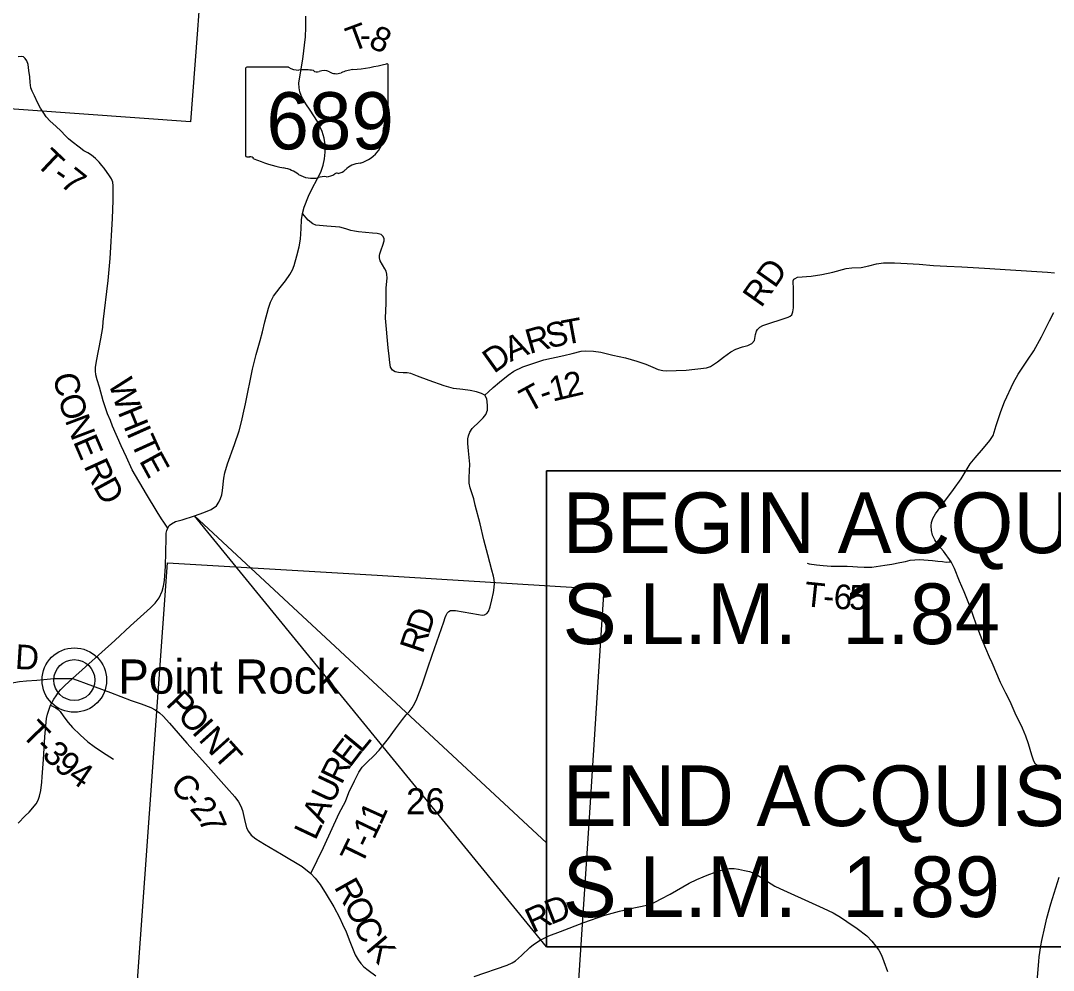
# Model space of a CAD drawing. Extents: x 0 to 34, y 0 to 22.
# Drawn here: x 4.807 to 7.19, y 15.87 to 18.062 of the extents above; entities that cross this region are included whole.
import ezdxf

# ---------------------------------------------------------------- set-up
doc = ezdxf.new("R2010")
doc.units = 0
for name, color, linetype in [('GM_X_Corporation', 7, 'Continuous'), ('GM_X_County_Road', 7, 'Continuous'), ('GM_X_County_Road_Text', 7, 'Continuous'), ('GM_X_Section_Text', 7, 'Continuous'), ('GM_X_State_Location', 7, 'Continuous'), ('GM_X_State_Route', 7, 'Continuous'), ('GM_X_State_Shield', 7, 'Continuous'), ('GM_X_Township_Road', 7, 'Continuous'), ('GM_X_Township_Road_Text', 7, 'Continuous'), ('GM_X_Unincorporated', 7, 'Continuous'), ('GM_X_Unincorporated_Location', 7, 'Continuous'), ('GM_X_Unincorporated_Text', 7, 'Continuous'), ('SH_Text', 7, 'Continuous')]:
    doc.layers.add(name, color=color, linetype=linetype)

msp = doc.modelspace()

# ---------------------------------------------------------------- linework, layer by layer
at = {"layer": 'GM_X_Corporation'}
for points in [[(4.2512, 18.9319), (5.2756, 18.8667), (5.2491, 18.5021), (5.2146, 18.0305), (5.1989, 17.8285), (4.1811, 17.9012)], [(5.6294, 16.7819), (6.1525, 16.7497), (6.1454, 16.6317), (6.1179, 16.2098), (6.0868, 15.7303), (5.0732, 15.7926), (5.1457, 16.8107)]]:
    msp.add_lwpolyline(points, close=True, dxfattribs=at)
at = {"layer": 'GM_X_County_Road'}
for points in [[(7.1909, 16.327), (7.1802, 16.3307), (7.1695, 16.334), (7.1616, 16.3368), (7.1555, 16.3402), (7.1492, 16.3456), (7.1452, 16.3526), (7.1401, 16.3664), (7.1328, 16.3928), (7.1263, 16.4101), (7.1191, 16.4285), (7.1023, 16.4635), (7.0901, 16.4901), (7.0803, 16.5099), (7.0679, 16.534), (7.0486, 16.5795), (7.043, 16.593), (7.0261, 16.633), (7.0121, 16.6691), (6.9977, 16.7091), (6.9839, 16.7432), (6.9738, 16.7684), (6.9622, 16.7971), (6.9542, 16.8131), (6.9365, 16.8372), (6.9237, 16.8522), (6.9165, 16.8634), (6.9113, 16.8741), (6.9085, 16.885), (6.908, 16.8956), (6.9092, 16.9033), (6.9123, 16.9129), (6.9181, 16.9236), (6.9304, 16.9402), (6.9594, 16.9794), (6.9773, 17.0044), (6.9984, 17.0387), (7.0093, 17.0527), (7.0289, 17.0751), (7.0432, 17.093), (7.0509, 17.1047), (7.0584, 17.1273), (7.0686, 17.1598), (7.0772, 17.1817), (7.098, 17.227), (7.1088, 17.2457), (7.1302, 17.2782), (7.1447, 17.2997), (7.1625, 17.332), (7.1811, 17.3688), (7.1912, 17.3879)], [(4.9265, 16.5431), (4.9376, 16.5393), (4.9583, 16.5323), (5.0141, 16.5112), (5.0619, 16.493), (5.0852, 16.4849), (5.1073, 16.4762), (5.1176, 16.4708), (5.1272, 16.4645), (5.1361, 16.4563), (5.1506, 16.4406), (5.1905, 16.3943), (5.2337, 16.3465), (5.2817, 16.292), (5.3015, 16.2702), (5.3096, 16.2587), (5.3148, 16.2491), (5.3188, 16.2385), (5.3235, 16.2178), (5.3282, 16.199), (5.3329, 16.1905), (5.3393, 16.1822), (5.3499, 16.1734), (5.3696, 16.1611), (5.4086, 16.1383), (5.4563, 16.1093), (5.4768, 16.0933), (5.487, 16.0828), (5.4981, 16.0676), (5.5121, 16.0457), (5.5294, 16.0163), (5.543, 15.9915), (5.55, 15.9764), (5.5579, 15.9586), (5.5663, 15.9366), (5.5789, 15.9056), (5.5861, 15.894), (5.5924, 15.8853), (5.5992, 15.8783), (5.6088, 15.8699), (5.6263, 15.8573)], [(5.8536, 15.8557), (5.9295, 15.8818), (5.9414, 15.8871), (5.9486, 15.8921), (5.9624, 15.9044), (5.982, 15.9222), (5.9905, 15.9296), (6.0056, 15.9392), (6.0262, 15.9497), (6.0525, 15.9595), (6.1064, 15.9803), (6.1553, 15.9974), (6.1891, 16.0065), (6.2222, 16.0142), (6.2412, 16.0177), (6.261, 16.0226), (6.272, 16.0277), (6.2853, 16.0349), (6.3058, 16.0459), (6.3499, 16.0707), (6.3676, 16.0795), (6.3821, 16.086), (6.3954, 16.0909), (6.4209, 16.1), (6.4337, 16.1031), (6.4423, 16.105), (6.4535, 16.1052), (6.4638, 16.1033), (6.4772, 16.1003), (6.4888, 16.0977), (6.5009, 16.093), (6.5147, 16.0849), (6.5304, 16.0746), (6.5471, 16.0643), (6.5591, 16.0587), (6.5845, 16.0471), (6.6162, 16.0326), (6.659, 16.0137), (6.6816, 16.0029), (6.6986, 15.9927), (6.7134, 15.9829), (6.737, 15.9665), (6.7596, 15.9493), (6.7708, 15.9371), (6.7797, 15.9266), (6.7871, 15.9164), (6.7936, 15.9051), (6.7988, 15.8902), (6.8072, 15.8669)], [(7.1436, 15.7943), (7.1457, 15.802), (7.1491, 15.8155), (7.1519, 15.8304), (7.1527, 15.843), (7.1545, 15.8633), (7.1562, 15.8902), (7.1573, 15.901), (7.1608, 15.9262), (7.1632, 15.9388), (7.1702, 15.9695), (7.1749, 15.9905), (7.1844, 16.0237), (7.2038, 16.0846)]]:
    msp.add_lwpolyline(points, dxfattribs=at)
at = {"layer": 'GM_X_State_Route'}
msp.add_lwpolyline([(4.801, 16.2093), (4.8174, 16.2261), (4.8265, 16.2347), (4.8426, 16.2541), (4.8472, 16.2625), (4.8503, 16.2718), (4.8535, 16.285), (4.856, 16.3039), (4.857, 16.3162), (4.8586, 16.3365), (4.8596, 16.3568), (4.8631, 16.4088), (4.8669, 16.4512), (4.8688, 16.4615), (4.872, 16.4705), (4.8757, 16.4816), (4.8836, 16.4958), (4.8888, 16.5037), (4.8945, 16.5116), (4.9, 16.5183), (4.9093, 16.5275), (4.9265, 16.5431), (5.0242, 16.6312), (5.0608, 16.6651), (5.1065, 16.7067), (5.1175, 16.7177), (5.1265, 16.7299), (5.1336, 16.745), (5.1367, 16.7568), (5.1391, 16.7698), (5.1411, 16.8028), (5.1425, 16.867), (5.1427, 16.8789), (5.1444, 16.8853), (5.1465, 16.8908), (5.1498, 16.8964), (5.1554, 16.9008), (5.1642, 16.9058), (5.1796, 16.9098), (5.2085, 16.9189), (5.2301, 16.9263), (5.2467, 16.9335), (5.2586, 16.9421), (5.2644, 16.9502), (5.268, 16.9587), (5.2709, 16.9672), (5.2725, 16.9774), (5.2762, 17.0059), (5.2779, 17.0183), (5.284, 17.039), (5.3002, 17.0833), (5.3109, 17.1155), (5.3173, 17.1389), (5.3208, 17.1533), (5.3261, 17.1777), (5.3418, 17.2572), (5.3507, 17.2912), (5.3595, 17.3234), (5.3649, 17.3437), (5.3708, 17.3665), (5.379, 17.3981), (5.3834, 17.4119), (5.3905, 17.4258), (5.4057, 17.4459), (5.4182, 17.4615), (5.4281, 17.4757), (5.434, 17.4868), (5.4383, 17.4964), (5.4445, 17.519), (5.45, 17.5399), (5.4525, 17.5578), (5.4544, 17.582), (5.4552, 17.6023), (5.4574, 17.6164), (5.4613, 17.6314), (5.4714, 17.6569), (5.479, 17.6727), (5.4921, 17.6977), (5.4995, 17.7119), (5.505, 17.7283), (5.5083, 17.7427), (5.5096, 17.7585), (5.5096, 17.7761), (5.5075, 17.7907), (5.5028, 17.8057), (5.4917, 17.8288), (5.4751, 17.8555), (5.4648, 17.8701), (5.4583, 17.8814), (5.4544, 17.8894), (5.4513, 17.8974), (5.4494, 17.907), (5.449, 17.9179), (5.4544, 17.9507), (5.4578, 17.9733), (5.464, 18.0242), (5.4654, 18.0462), (5.4648, 18.0726)], dxfattribs=at)
at = {"layer": 'GM_X_State_Shield'}
for p, q in [((5.3257, 17.9508), (5.3257, 17.7506)), ((5.4254, 17.9542), (5.3289, 17.9542)), ((5.6552, 17.8545), (5.6552, 17.9592)), ((5.6552, 17.8545), (5.6552, 17.8545))]:
    msp.add_line(p, q, dxfattribs=at)
for centre, major_axis, start_param, end_param in [((5.3294, 17.9512), (0.00382, 0), 1.712693, 3.28349), ((5.4484, 17.9774), (0.037, 0), 4.042523, 4.731795), ((5.4607, 17.8419), (0.133, 0), 1.404758, 1.657858), ((5.4909, 17.9522), (0.0107, 0), 3.836095, 5.185415), ((5.5066, 17.9291), (0.0222, 0), 0.950623, 2.079405), ((5.5824, 17.8931), (0.0703, 0), 1.699011, 2.107814), ((5.5378, 18.227), (0.3495, 0), 4.814394, 5.042369), ((5.6516, 17.9596), (0.00367, 0), 6.141152, 7.989035), ((5.5352, 17.9608), (0.0267, 0), 4.081561, 5.145723), ((5.6544, 17.8468), (0.00568, 0), 1.883978, 3.671073), ((5.6513, 17.8541), (0.00393, 0), 5.05454, 6.418171), ((5.6183, 17.8336), (0.0341, 0), 5.934695, 6.695948), ((5.5574, 17.7974), (0.0874, 0), 5.101752, 6.440018), ((5.6684, 17.8107), (0.0248, 0), 2.387724, 3.262537), ((5.3295, 17.7502), (0.00385, 0), 3.00124, 4.508301), ((5.3301, 17.7707), (0.0294, 0), 4.665946, 4.897461), ((5.3361, 17.7391), (0.0106, 0), 0.519207, 1.627899), ((5.4699, 17.9189), (0.2524, 0), 4.195997, 4.488961), ((5.5943, 17.6945), (0.0479, 0), 1.647645, 2.488434), ((5.3946, 17.6607), (0.079, 0), 0.823519, 1.323587), ((5.4801, 17.7381), (0.0501, 0), 4.026481, 4.996735), ((5.5127, 17.7231), (0.0267, 0), 4.691044, 5.507374), ((5.5368, 17.7037), (0.00752, 0), 1.147584, 2.315152), ((5.5336, 17.7313), (0.0282, 0), 4.937069, 5.64225), ((5.509, 17.6689), (0.0412, 0), 1.495662, 1.94098)]:
    msp.add_ellipse(centre, major_axis=major_axis, ratio=0.8, start_param=start_param, end_param=end_param, dxfattribs=at)
at = {"layer": 'GM_X_Township_Road'}
for points in [[(5.1465, 16.8908), (5.1375, 16.9044), (5.132, 16.9122), (5.1219, 16.9278), (5.0973, 16.9688), (5.0642, 17.025), (5.0511, 17.0544), (5.0392, 17.0806), (5.0191, 17.1258), (5.0144, 17.1387), (5.0078, 17.1545), (4.9974, 17.1843), (4.9889, 17.2157), (4.9835, 17.2332), (4.9803, 17.2446), (4.9797, 17.2538), (4.9799, 17.2611), (4.9824, 17.2758), (4.9917, 17.3278), (4.9963, 17.354), (4.9976, 17.3667), (5.009, 17.4623), (5.0138, 17.513), (5.0189, 17.6054), (5.0203, 17.6466), (5.0207, 17.6692), (5.0205, 17.6809), (5.0195, 17.6891), (5.0166, 17.6967), (5.0119, 17.7039), (4.9998, 17.7211), (4.9941, 17.7279), (4.9881, 17.7353), (4.9801, 17.7439), (4.9703, 17.7517), (4.9619, 17.7568), (4.9528, 17.7617), (4.9421, 17.7695), (4.9259, 17.7821), (4.9175, 17.789), (4.9094, 17.7967), (4.9005, 17.8067), (4.8886, 17.818), (4.8753, 17.8299), (4.8662, 17.8399), (4.8602, 17.8484), (4.8527, 17.8602), (4.8461, 17.8726), (4.8387, 17.8884), (4.8334, 17.8988), (4.8306, 17.907), (4.8291, 17.9193), (4.8281, 17.9323), (4.8262, 17.9468), (4.8246, 17.9606), (4.8215, 17.9692), (4.8178, 17.9743), (4.8133, 17.978), (4.8079, 17.9791), (4.8016, 17.9782)], [(5.4768, 16.0933), (5.506, 16.1531), (5.5421, 16.2323), (5.5565, 16.2594), (5.5646, 16.2807), (5.5777, 16.3075), (5.5874, 16.3276), (5.5953, 16.3387), (5.6066, 16.3506), (5.6222, 16.3649), (5.6342, 16.3777), (5.6555, 16.4051), (5.6717, 16.4274), (5.6879, 16.4491), (5.6966, 16.4593), (5.7039, 16.4664), (5.7101, 16.4755), (5.7138, 16.4808), (5.7174, 16.4877), (5.7213, 16.4968), (5.7332, 16.529), (5.7465, 16.5682), (5.757, 16.597), (5.7835, 16.6744), (5.7866, 16.6841), (5.7887, 16.6894), (5.7909, 16.6943), (5.7948, 16.6984), (5.7989, 16.7001), (5.8045, 16.7007), (5.8106, 16.7003), (5.8634, 16.6908), (5.872, 16.6894), (5.8776, 16.6902), (5.8829, 16.6933), (5.8866, 16.6982), (5.8905, 16.7085), (5.8944, 16.7253), (5.8983, 16.7421), (5.8998, 16.7537), (5.9002, 16.7637), (5.9, 16.7717), (5.8979, 16.78), (5.8942, 16.7935), (5.8848, 16.8292), (5.8759, 16.8635), (5.8675, 16.9005), (5.8562, 16.9432), (5.8527, 16.9584), (5.8443, 16.9836), (5.8423, 16.9947), (5.8421, 17.0075), (5.8439, 17.0385), (5.8406, 17.0686), (5.8392, 17.0855), (5.839, 17.0963), (5.8404, 17.1036), (5.8435, 17.1124), (5.8492, 17.1208), (5.8661, 17.1366), (5.8741, 17.1452), (5.8807, 17.1528), (5.8846, 17.1627), (5.8842, 17.1744), (5.8827, 17.1888), (5.8778, 17.1972), (5.8702, 17.2015), (5.8589, 17.2048), (5.8441, 17.2085), (5.8271, 17.2103), (5.8057, 17.2132), (5.7846, 17.2192), (5.7497, 17.2311), (5.7228, 17.2413), (5.7076, 17.2471), (5.6992, 17.2487), (5.6897, 17.2491), (5.6788, 17.2495), (5.6712, 17.2516), (5.6649, 17.2555), (5.6607, 17.2617), (5.6586, 17.2729), (5.6577, 17.2873), (5.6554, 17.3068), (5.6493, 17.3752), (5.6501, 17.4099), (5.6507, 17.4452), (5.6527, 17.4672), (5.6519, 17.4768), (5.6503, 17.4838), (5.6476, 17.4894), (5.6419, 17.498), (5.6369, 17.5073), (5.6354, 17.5143), (5.6352, 17.52), (5.6359, 17.5238), (5.6389, 17.5331), (5.6431, 17.5439), (5.6461, 17.5534), (5.6456, 17.5594), (5.6428, 17.5646), (5.6388, 17.5684), (5.6298, 17.5706), (5.6191, 17.5714), (5.5867, 17.5745), (5.5774, 17.5757), (5.5693, 17.5777), (5.5577, 17.5815), (5.5434, 17.5852), (5.5138, 17.5875), (5.4967, 17.5887), (5.4884, 17.59), (5.4815, 17.5929), (5.4706, 17.6015), (5.4574, 17.6164)], [(5.8778, 17.1972), (5.8866, 17.2048), (5.8977, 17.2148), (5.9121, 17.2276), (5.9318, 17.2438), (5.9449, 17.2526), (5.9661, 17.2625), (5.9932, 17.2723), (6.0145, 17.2791), (6.0601, 17.289), (6.08, 17.2937), (6.1007, 17.299), (6.1107, 17.3001), (6.1287, 17.2993), (6.1457, 17.297), (6.1732, 17.2901), (6.2024, 17.2839), (6.229, 17.2762), (6.2498, 17.2688), (6.2657, 17.2619), (6.2779, 17.257), (6.2892, 17.2545), (6.2982, 17.2537), (6.3194, 17.2541), (6.3429, 17.255), (6.3894, 17.2607), (6.3988, 17.2639), (6.4149, 17.2746), (6.4286, 17.2852), (6.4458, 17.2972), (6.4576, 17.3037), (6.4725, 17.3088), (6.4854, 17.3117), (6.4941, 17.3164), (6.5001, 17.3235), (6.5031, 17.3376), (6.505, 17.3452), (6.5076, 17.3493), (6.5125, 17.3542), (6.5197, 17.3581), (6.5783, 17.3777), (6.5825, 17.3799), (6.5862, 17.3827), (6.5885, 17.3897), (6.5903, 17.3993), (6.5903, 17.4411), (6.5895, 17.4616), (6.5909, 17.4652), (6.5944, 17.4671), (6.5999, 17.4699), (6.6309, 17.4724), (6.6561, 17.4763), (6.681, 17.481), (6.7118, 17.4895), (6.7253, 17.4916), (6.7463, 17.4922), (6.764, 17.4959), (6.7818, 17.5008), (6.7983, 17.503), (6.8232, 17.5032), (6.8529, 17.5014), (6.8806, 17.5001), (6.9131, 17.4965), (6.9439, 17.4954), (6.9786, 17.4938), (7.0311, 17.4907), (7.0913, 17.4868), (7.1763, 17.4815), (7.1926, 17.48)], [(6.6221, 16.8099), (6.6267, 16.8083), (6.6438, 16.8059), (6.659, 16.8043), (6.6777, 16.8024), (6.6951, 16.8024), (6.714, 16.8024), (6.7271, 16.802), (6.7384, 16.8012), (6.7533, 16.8005), (6.7626, 16.8001), (6.7712, 16.8008), (6.8013, 16.8048), (6.817, 16.8071), (6.8357, 16.811), (6.8488, 16.8139), (6.86, 16.8164), (6.8705, 16.8176), (6.8817, 16.8178), (6.8914, 16.8174), (6.9111, 16.8157), (6.9237, 16.8146), (6.9344, 16.8132), (6.943, 16.8122), (6.9494, 16.8124), (6.9542, 16.8131)], [(4.7741, 16.5345), (4.7751, 16.5342), (4.7815, 16.5329), (4.7867, 16.5331), (4.7916, 16.534), (4.8041, 16.5363), (4.8204, 16.5378), (4.844, 16.5399), (4.8608, 16.5408), (4.8834, 16.5431), (4.9095, 16.5435), (4.9265, 16.5431)], [(4.8757, 16.4816), (4.8807, 16.4794), (4.8886, 16.4755), (4.8933, 16.4717), (4.898, 16.467), (4.9053, 16.4575), (4.909, 16.4518), (4.917, 16.442), (4.9264, 16.4307), (4.9446, 16.4134), (4.9623, 16.3976), (4.9765, 16.3868), (4.9962, 16.3737), (5.0212, 16.3576)]]:
    msp.add_lwpolyline(points, dxfattribs=at)
at = {"layer": 'GM_X_Unincorporated'}
for radius in [0.0744, 0.0472]:
    msp.add_circle((4.9309, 16.5398), radius, dxfattribs=at)
at = {"layer": 'GM_X_Unincorporated_Location'}
msp.add_line((4.9309, 16.5398), (4.9309, 16.5398), dxfattribs=at)
at = {"layer": 'SH_Text'}
for points in [[(8.0965, 17.0228), (6.0206, 17.0228), (6.0206, 15.9239), (8.0965, 15.9239)], [(6.0206, 17.0228), (8.0965, 17.0228), (8.0965, 15.9239), (6.0206, 15.9239)], [(5.2085, 16.9189), (6.0206, 16.1639), (6.0206, 15.9239)]]:
    msp.add_lwpolyline(points, close=True, dxfattribs=at)

# ---------------------------------------------------------------- texts
at = {"layer": 'GM_X_County_Road_Text'}
for s, rotation, p in [('P', 314.1466, (5.1402, 16.483)), ('O', 312.1074, (5.1665, 16.4559)), ('I', 311.9988, (5.2, 16.4188)), ('N', 312.0054, (5.2156, 16.4014)), ('T', 312.0031, (5.2491, 16.3643)), ('C', 310.991, (5.1494, 16.2946)), ('-', 310.9869, (5.18, 16.2593)), ('2', 310.901, (5.1953, 16.2417)), ('7', 293.6035, (5.2158, 16.2191)), ('R', 299.2908, (5.5291, 16.0622)), ('O', 296.7117, (5.5516, 16.0221)), ('D', 21.1845, (6.03, 15.9745)), ('R', 24.8839, (5.9885, 15.9552)), ('C', 292.3127, (5.5736, 15.9785)), ('K', 310.1332, (5.6013, 15.9188))]:
    msp.add_text(s, height=0.0568, rotation=rotation, dxfattribs=at).set_placement(p)
at = {"layer": 'GM_X_Section_Text'}
msp.add_text('26', height=0.06, rotation=0, dxfattribs=at).set_placement((5.6964, 16.2302))
at = {"layer": 'GM_X_State_Location'}
for s in ['s', 'r']:
    msp.add_text(s, height=0.000189, dxfattribs=at).set_placement((5.2883, 17.0267))
msp.add_text('689', height=0.000189, rotation=0, dxfattribs=at).set_placement((5.2214, 17.0129))
at = {"layer": 'GM_X_State_Shield'}
msp.add_text('689', height=0.13184, dxfattribs=at).set_placement((5.3741, 17.7648))
at = {"layer": 'GM_X_Township_Road_Text'}
for s, height, rotation, p in [('T', 0.0568, 20.3624, (5.5712, 17.9894)), ('8', 0.0568, 335.8293, (5.6072, 18.0019)), ('-', 0.0568, 0.6334, (5.5902, 18.0004)), ('T', 0.0568, 316.7746, (4.8393, 17.7304)), ('-', 0.0568, 324.9897, (4.8771, 17.6958)), ('7', 0.0568, 321.5011, (4.8955, 17.683)), ('RD', 0.05682, 54.8048, (6.5157, 17.3972)), ('T', 0.0568, 10.4022, (6.0622, 17.3133)), ('R', 0.0568, 15.9298, (5.9814, 17.2921)), ('S', 0.0568, 13.1627, (6.0256, 17.3048)), ('A', 0.0568, 22.5036, (5.9368, 17.2736)), ('D', 0.0568, 35.5504, (5.8991, 17.2461)), ('2', 0.0568, 13.1452, (6.0684, 17.1905)), ('C', 0.0568, 280.4832, (4.8821, 17.2441)), ('W', 0.0568, 287.5425, (5.009, 17.2263)), ('1', 0.0568, 13.8141, (6.0345, 17.1822)), ('T', 0.0568, 28.6737, (5.9788, 17.1557)), ('-', 0.0568, 18.7213, (6.0137, 17.175)), ('O', 0.0568, 287.3918, (4.8924, 17.1909)), ('H', 0.0568, 292.2312, (5.0305, 17.1588)), ('N', 0.0568, 290.6856, (4.9085, 17.1398)), ('I', 0.0568, 294.0153, (5.0502, 17.1108)), ('T', 0.0568, 294.3803, (5.0599, 17.0891)), ('E', 0.0568, 293.3705, (4.9273, 17.0904)), ('E', 0.0568, 298.6442, (5.0794, 17.0463)), ('R', 0.0568, 294.5064, (4.9518, 17.0343)), ('D', 0.0568, 298.7457, (4.9732, 16.9877)), ('T', 0.0568, 354.0408, (6.6131, 16.7108)), ('6', 0.0568, 357.3237, (6.6821, 16.7045)), ('5', 0.0568, 358.2298, (6.7181, 16.7029)), ('-', 0.0568, 356.1262, (6.6576, 16.7062)), ('D', 0.0568, 71.3531, (5.7491, 16.6431)), ('R', 0.0568, 71.5626, (5.7344, 16.5989)), ('D', 0.0568, 356.404, (4.793, 16.5659)), ('T', 0.0568, 314.1, (4.8064, 16.4132)), ('-', 0.0568, 314.6019, (4.8364, 16.3823)), ('3', 0.0568, 316.1835, (4.854, 16.3645)), ('E', 0.0568, 52.7144, (5.5668, 16.336)), ('L', 0.0568, 50.3793, (5.5921, 16.3694)), ('9', 0.0568, 318.8182, (4.8813, 16.3384)), ('R', 0.0568, 63.9813, (5.5479, 16.2966)), ('4', 0.0568, 325.7973, (4.9136, 16.3107)), ('U', 0.0568, 64.6781, (5.5265, 16.2516)), ('A', 0.0568, 64.6816, (5.5052, 16.2064)), ('1', 0.0568, 65.762, (5.6382, 16.2027)), ('L', 0.0568, 64.6808, (5.487, 16.1679)), ('1', 0.0568, 64.4239, (5.6224, 16.1698)), ('T', 0.0568, 63.9869, (5.5934, 16.1102)), ('-', 0.0568, 64.0741, (5.6121, 16.1485))]:
    msp.add_text(s, height=height, rotation=rotation, dxfattribs=at).set_placement(p)
at = {"layer": 'GM_X_Unincorporated_Text'}
msp.add_text('Point Rock', height=0.07898, rotation=0, dxfattribs=at).set_placement((5.0323, 16.5084))
at = {"layer": 'SH_Text'}
for s, p in [('BEGIN ACQUISITION', (6.0576, 16.8328)), ('S.L.M.  1.84', (6.0576, 16.6228)), ('END ACQUISITION', (6.0576, 16.2028)), ('S.L.M.  1.89', (6.0576, 15.9928))]:
    msp.add_text(s, height=0.14, dxfattribs=at).set_placement(p)

doc.saveas('drawing.dxf')
